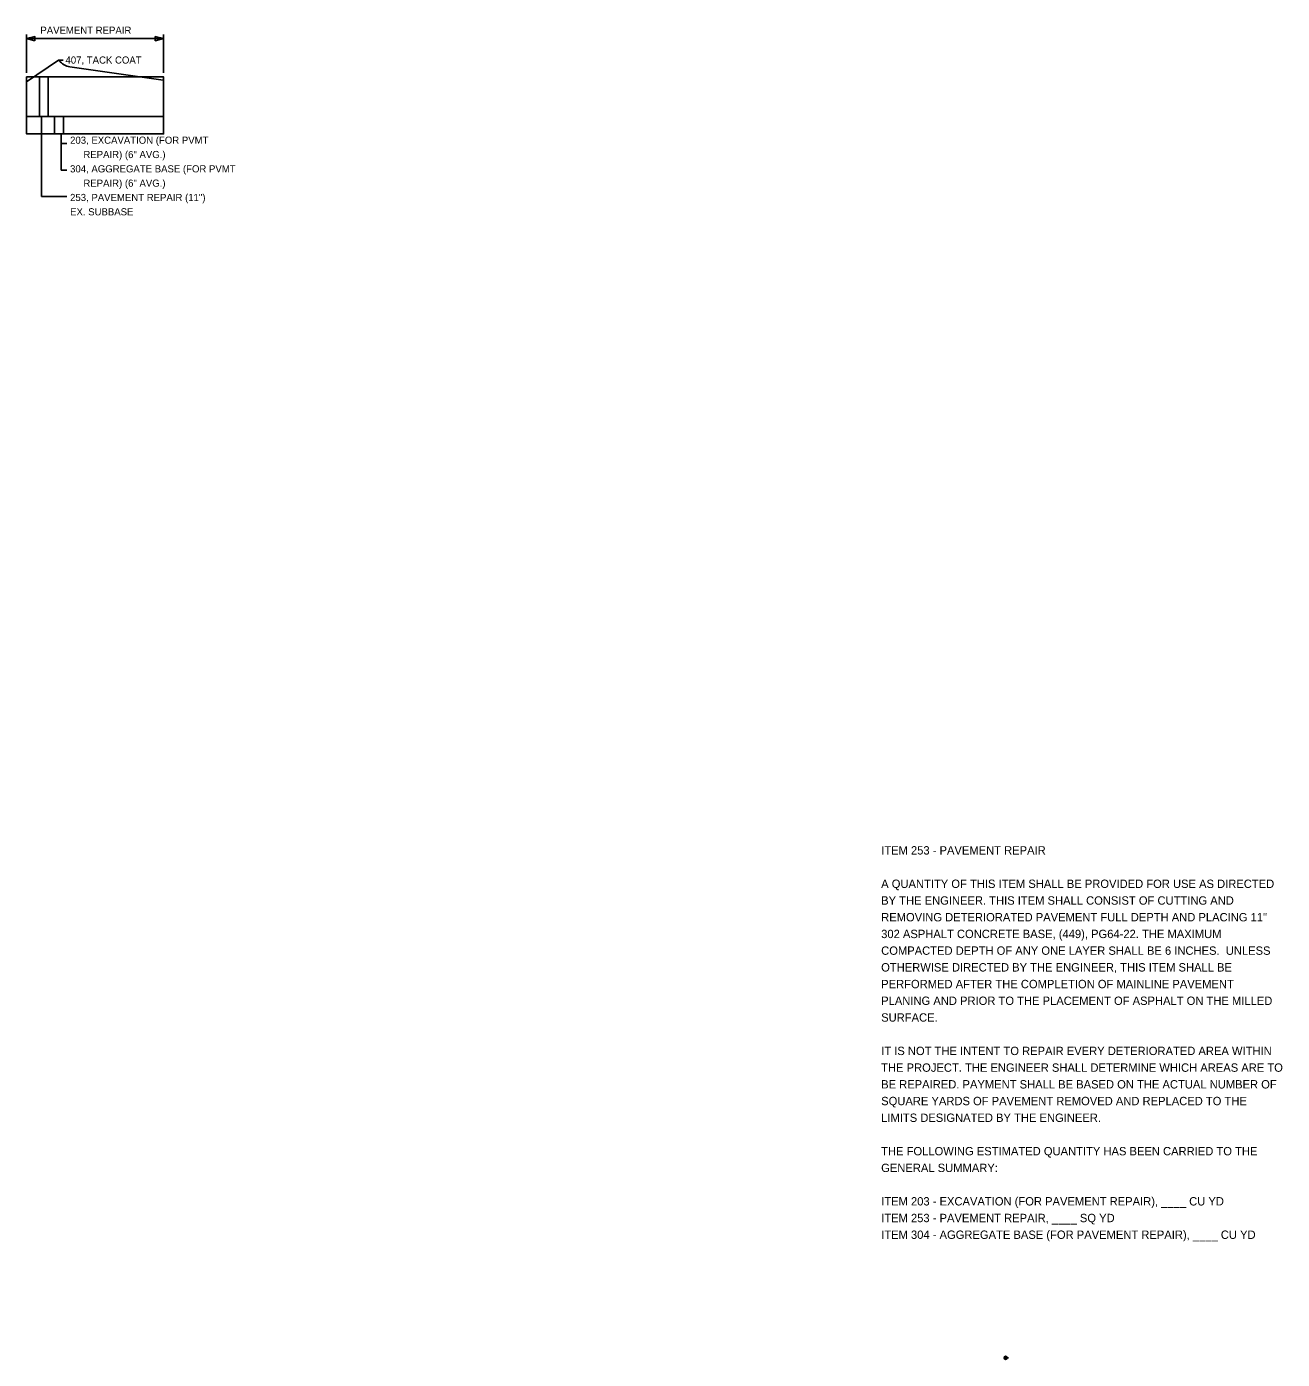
# Model space of a CAD drawing. Extents: x 0 to 74, y -27.6 to 51.8.
# Drawn here: x 52.92 to 73.96, y -1.18 to 21.15 of the extents above; entities that cross this region are included whole.
import ezdxf

# ---------------------------------------------------------------- set-up
doc = ezdxf.new("R2010")
doc.units = 0
for name, color, linetype in [('Level 4', 7, 'Continuous'), ('Level 6', 7, 'Continuous'), ('Level 7', 7, 'Continuous'), ('Level 9', 7, 'Continuous')]:
    doc.layers.add(name, color=color, linetype=linetype)

msp = doc.modelspace()

# ---------------------------------------------------------------- linework, layer by layer
at = {"layer": 'Level 6'}
for p, q in [((69.299, -1.152), (69.351, -1.152)), ((69.326, -1.152), (69.375, -1.152))]:
    msp.add_line(p, q, dxfattribs=at)
msp.add_circle((69.325, -1.152), 0.026, dxfattribs=at)
at = {"layer": 'Level 7'}
for p, q in [((52.923, 20.309), (52.923, 19.353)), ((55.218, 20.309), (55.218, 19.353))]:
    msp.add_line(p, q, dxfattribs=at)
for points in [[(52.923, 19.647), (55.218, 19.647), (55.218, 20.309), (52.923, 20.309)], [(52.923, 19.647), (55.218, 19.647), (55.218, 19.353), (52.923, 19.353)]]:
    msp.add_lwpolyline(points, close=True, dxfattribs=at)
at = {"layer": 'Level 9'}
for p, q in [((52.923, 20.379), (52.923, 21.021)), ((55.218, 20.379), (55.218, 21.021)), ((52.923, 20.951), (55.218, 20.951)), ((52.923, 20.229), (53.455, 20.592)), ((53.535, 20.592), (53.455, 20.592)), ((53.455, 20.592), (53.464, 20.582)), ((53.648, 20.476), (55.209, 20.255)), ((53.172, 19.647), (53.172, 18.303)), ((53.501, 19.353), (53.501, 18.747)), ((53.595, 19.191), (53.501, 19.191)), ((53.595, 18.747), (53.501, 18.747)), ((53.595, 18.303), (53.172, 18.303))]:
    msp.add_line(p, q, dxfattribs=at)
for points in [[(53.063, 20.916), (52.923, 20.951), (53.063, 20.986)], [(55.078, 20.986), (55.218, 20.951), (55.078, 20.916)], [(53.136, 20.309), (53.284, 20.309), (53.284, 19.647), (53.136, 19.647)], [(53.391, 19.647), (53.54, 19.647), (53.54, 19.353), (53.391, 19.353)]]:
    msp.add_lwpolyline(points, close=True, dxfattribs=at)
msp.add_ellipse((53.7, 20.852), major_axis=(0, -0.38), ratio=0.880535, start_param=5.503204, end_param=6.130041, dxfattribs=at)

# ---------------------------------------------------------------- texts
at = {"layer": 'Level 4'}
for s, p in [('ITEM 253 - PAVEMENT REPAIR', (67.24, 7.28)), ('A QUANTITY OF THIS ITEM SHALL BE PROVIDED FOR USE AS DIRECTED ', (67.24, 6.72)), ('BY THE ENGINEER. THIS ITEM SHALL CONSIST OF CUTTING AND ', (67.24, 6.44)), ('REMOVING DETERIORATED PAVEMENT FULL DEPTH AND PLACING 11" ', (67.24, 6.16)), ('302 ASPHALT CONCRETE BASE, (449), PG64-22. THE MAXIMUM ', (67.24, 5.88)), ('COMPACTED DEPTH OF ANY ONE LAYER SHALL BE 6 INCHES.  UNLESS ', (67.24, 5.6)), ('OTHERWISE DIRECTED BY THE ENGINEER, THIS ITEM SHALL BE ', (67.24, 5.32)), ('PERFORMED AFTER THE COMPLETION OF MAINLINE PAVEMENT ', (67.24, 5.04)), ('PLANING AND PRIOR TO THE PLACEMENT OF ASPHALT ON THE MILLED ', (67.24, 4.76)), ('SURFACE.', (67.24, 4.48)), ('IT IS NOT THE INTENT TO REPAIR EVERY DETERIORATED AREA WITHIN ', (67.24, 3.92)), ('THE PROJECT. THE ENGINEER SHALL DETERMINE WHICH AREAS ARE TO ', (67.24, 3.64)), ('BE REPAIRED. PAYMENT SHALL BE BASED ON THE ACTUAL NUMBER OF ', (67.24, 3.36)), ('SQUARE YARDS OF PAVEMENT REMOVED AND REPLACED TO THE ', (67.24, 3.08)), ('LIMITS DESIGNATED BY THE ENGINEER.', (67.24, 2.8)), ('THE FOLLOWING ESTIMATED QUANTITY HAS BEEN CARRIED TO THE ', (67.24, 2.24)), ('GENERAL SUMMARY:', (67.24, 1.96)), ('ITEM 203 - EXCAVATION (FOR PAVEMENT REPAIR), ____ CU YD', (67.24, 1.4)), ('ITEM 253 - PAVEMENT REPAIR, ____ SQ YD', (67.24, 1.12)), ('ITEM 304 - AGGREGATE BASE (FOR PAVEMENT REPAIR), ____ CU YD', (67.24, 0.84))]:
    msp.add_text(s, height=0.14, dxfattribs=at).set_placement(p)
at = {"layer": 'Level 6'}
for s, p in [('P.11', (69.321, -1.162)), ('1', (69.324, -1.146)), ('Drawing', (69.358, -1.146)), ('1:1', (69.358, -1.162))]:
    msp.add_text(s, height=0.00328, dxfattribs=at).set_placement(p)
at = {"layer": 'Level 9'}
for s, p in [('PAVEMENT REPAIR', (53.153, 21.031)), ('407, TACK COAT', (53.574, 20.532)), ('203, EXCAVATION (FOR PVMT ', (53.651, 19.189)), ('     REPAIR) (6" AVG.)', (53.651, 18.949)), ('304, AGGREGATE BASE (FOR PVMT ', (53.651, 18.709)), ('     REPAIR) (6" AVG.)', (53.651, 18.469)), ('253, PAVEMENT REPAIR (11")', (53.651, 18.229)), ('EX. SUBBASE', (53.651, 17.989))]:
    msp.add_text(s, height=0.12, dxfattribs=at).set_placement(p)

doc.saveas('drawing.dxf')
